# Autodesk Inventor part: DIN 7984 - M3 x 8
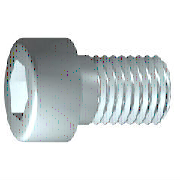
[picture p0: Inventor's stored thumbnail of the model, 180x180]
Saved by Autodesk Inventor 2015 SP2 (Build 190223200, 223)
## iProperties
IsCustomPart: 0
Created: 2012-02
Part Number: DIN 7984 - M3 x 8
Material: Stahl, weich
Description: Zylinderkopfschraube
Document SubType Name: Modeling
Standard: DIN 7984
Designer: rYan
Standard Revision: 1985
Standards Organization: DIN
Language: de-DE
Size Designation: M3 x 8
Categories: <MemberInstance><Categories><Category DisplayName="Verbindungselemente" InternalName="e4da775c-781d-43d5-af7c-5136215cf5a6" Mnemonic="FSTN"><Category DisplayNam
Density: 7.85 g/cm^3
Mass: 0.763378 g
Surface Area: 1.64326 cm^2
Volume: 0.0972456 cm^3
Appearance: Halbpoliert
Author: rYan
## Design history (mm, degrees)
sketch "Skizze1"
  geometry: L1 (0.167, 0)-(8, 0); L2 (8, 0)-(8, 1.5); L3 (8, 1.5)-(1.5, 1.5); L4 (1.5, 1.5)-(1.193, 1.5); L5 (1.193, 1.5)-(0, 1.5); L6 (0, 1.5)-(0, 2.75); L7 (0, 2.75)-(-2, 2.75); L8 (-2, 2.75)-(-2, 1.155); L9 (-2, 1.155)-(-0.5, 1.155); L10 (-0.5, 1.155)-(0.167, 0); L11 (-4, 0)-(10, 0) reference; L12 (0, -0.55)-(0, 3.3) reference; L13 (1.5, 1.5)-(0, 1.5)
  constraints: 22 end point, 6 parallel, 2 collinear, 2 perpendicular, 1 horizontal, 1 point on line
  dimensions: "d1" = 6.5 distance from line of L3.end L2 (= GEL); "d2" = 0.30683 distance of L4.end L3.end (computed from GAL); "d3" = 2 distance between parallel lines of L8 L6 (= KOH); "d4" = 1.5 distance of L8.end L9.end (= INTI); "d5" = 60 deg angle of L10 L1; "d6" = 3 diameter of L3 L1 (= GD); "d7" = 3 diameter of L5 L1 (= BDM); "d8" = 2.3094 diameter of L9 L1 (= 1.1547 x SW); "d9" = 5.5 diameter of L7 L1 (= KOD); "d26" = 8 distance between parallel lines of L12 L2 (= NLG)
revolve "Körper" sketch "Skizze1" stored, may be unused: angle "d10" = 90 deg
sketch "Skizze2"
  geometry: L1 (0, -3.85)-(0, 3.85) reference; L2 (-3.85, 0)-(3.85, 0) reference; L3 (1.155, 0)-(0.577, -1); L4 (0.577, -1)-(-0.577, -1); L5 (-0.577, -1)-(-1.155, 0); L6 (-1.155, 0)-(-0.577, 1); L7 (-0.577, 1)-(0.577, 1); L8 (0.577, 1)-(1.155, 0); 2 further points
  constraints: 12 end point, 1 coincident, 1 horizontal alignment, 1 point on line, 12 other
extrude "Loch" join sketch "Skizze2" stored distance "d11" = 10; taper "d12" = 0 deg
workplane "Work Plane1"
fillet "Fillet2" dims "d30" = 0.1 (= R)
body "Solid1"
fillet "Rundung1" dims "d17" = 0.3 (= RR)
feature "Gewinde" dims "d13" = 6.5 (= GEL), "d14" = 0
chamfer "Fase1" distance "d15" = 0.30673 (= -0.5 x SPD + 0.5 x GD); stored, may be unused: second distance "d16" = 0.30673 (= GUL), angle "d27" = 45 deg
other parameters: "GD" = 3 (= NND) [user parameter; used in 2 equation terms], "NLG" = 8 [user parameter; used in 1 equation term], "GEL" = 6.5 [user parameter; used in 2 equation terms], "KOD" = 5.5 [user parameter; used in 1 equation term], "KOH" = 2 [user parameter; used in 1 equation term], "INTI" = 1.5 [user parameter; used in 1 equation term], "GAL" = 0.30673 (= 0.61345 x PTC) [user parameter; used in 1 equation term], "GUL" = 0.30673 (= 0.61345 x PTC) [user parameter; used in 1 equation term], "BDM" = 3 (= NND) [user parameter; used in 1 equation term], "SW" = 2 [user parameter; used in 2 equation terms], "RR" = 0.3 [user parameter; used in 1 equation term], "SPD" = 2.38655 (= NND - 1.2269 x PTC) [user parameter; used in 1 equation term], "d19" = 0, "d28" = 0, "d29" = 0, "R" = 0.1 [user parameter; used in 1 equation term], "TOA" = 30 deg [user parameter], "GD1" = 2.38655 (= THREADDIA - 1.2269 x PTC) [user parameter], "THREADDIA" = 3 [user parameter; used in 1 equation term], "FAWI" = 45 deg [user parameter], "ANG" = 120 deg [user parameter], "PTC" = 0.5 [user parameter; used in 5 equation terms], "NND" = 3 [user parameter; used in 3 equation terms], "E0" = 2.31 (= 1.155 x SW) [user parameter]
